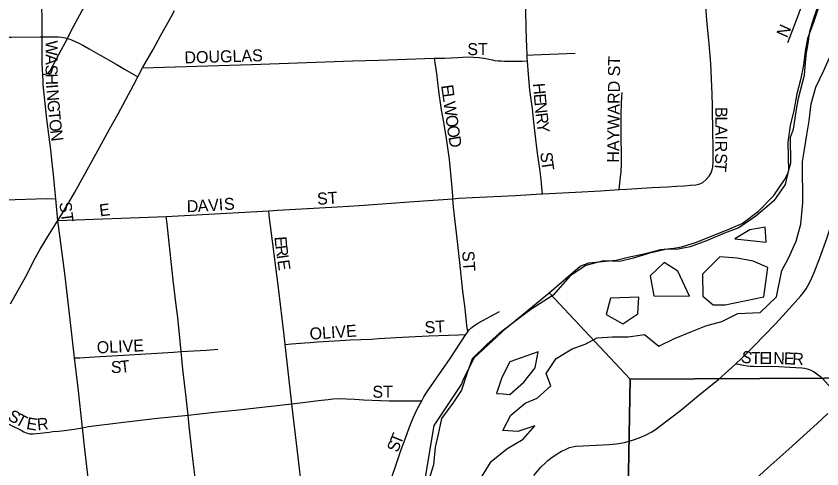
# Model space of a CAD drawing. Extents: x 0 to 34, y 0 to 22.
# Drawn here: x 5.7568 to 6.0752, y 18.8838 to 19.0628 of the extents above; entities that cross this region are included whole.
import ezdxf

# ---------------------------------------------------------------- set-up
doc = ezdxf.new("R2010")
doc.units = 0
for name, color, linetype in [('GM_X_City_Street', 7, 'Continuous'), ('GM_X_City_Street_Text', 7, 'Continuous'), ('GM_X_Major_River', 7, 'Continuous'), ('GM_X_Section', 7, 'Continuous'), ('GM_X_State_Route', 7, 'Continuous')]:
    doc.layers.add(name, color=color, linetype=linetype)

msp = doc.modelspace()

# ---------------------------------------------------------------- linework, layer by layer
at = {"layer": 'GM_X_City_Street'}
for points in [[(5.76711, 19.05456), (5.76711, 19.05656), (5.76711, 19.05942), (5.76698, 19.06897), (5.7669, 19.07523), (5.76683, 19.08435)], [(5.77708, 19.05392), (5.77875, 19.0572), (5.79185, 19.08163), (5.79313, 19.08386)], [(5.95868, 19.04734), (5.95857, 19.05106), (5.95851, 19.05324), (5.9579, 19.07557), (5.95782, 19.08191)], [(6.02935, 18.99807), (6.03057, 18.99952), (6.03139, 19.00086), (6.03185, 19.00197), (6.03209, 19.00319), (6.0322, 19.00528), (6.0322, 19.00854), (6.0322, 19.01186), (6.03208, 19.0161), (6.03191, 19.02734), (6.03185, 19.03193), (6.03128, 19.04398), (6.0306, 19.0518), (6.0303, 19.05455), (6.0302, 19.05579), (6.02994, 19.05856), (6.02972, 19.06102), (6.02913, 19.06877), (6.02892, 19.0756), (6.02877, 19.07964), (6.02867, 19.08201)], [(6.06164, 19.05235), (6.06351, 19.05704), (6.06599, 19.06372), (6.06834, 19.07008), (6.07139, 19.07917), (6.07215, 19.08178)], [(5.71316, 19.05394), (5.72122, 19.0542), (5.72943, 19.05429), (5.74165, 19.05446), (5.75484, 19.05446), (5.76633, 19.05454), (5.76711, 19.05456)], [(5.76711, 19.05456), (5.77163, 19.05463), (5.77263, 19.05461), (5.77352, 19.05456), (5.77479, 19.05442), (5.77616, 19.05417), (5.77708, 19.05392)], [(5.76731, 19.03975), (5.76723, 19.04135), (5.76712, 19.04442), (5.76711, 19.04751), (5.76711, 19.05456)], [(5.76731, 19.03975), (5.76828, 19.03983), (5.76868, 19.03993), (5.76901, 19.04005), (5.76938, 19.04028), (5.76968, 19.0405), (5.77001, 19.04085), (5.77025, 19.0412), (5.77263, 19.04567), (5.77465, 19.04928), (5.77637, 19.05253), (5.77708, 19.05392)], [(5.77708, 19.05392), (5.7772, 19.05389), (5.77799, 19.05368), (5.77874, 19.05334), (5.78154, 19.05205), (5.78321, 19.05123), (5.78566, 19.0499), (5.78942, 19.04775), (5.79635, 19.04379), (5.79969, 19.04183), (5.80311, 19.03978), (5.80488, 19.03872)], [(5.9221, 19.04609), (5.92609, 19.04619), (5.93132, 19.04643), (5.93333, 19.04656), (5.93495, 19.04664), (5.93736, 19.04655), (5.93977, 19.04635), (5.94067, 19.04625), (5.94156, 19.04612), (5.94244, 19.04597), (5.94359, 19.04575), (5.94497, 19.04544), (5.94587, 19.04525), (5.9472, 19.04512), (5.94843, 19.04507), (5.94982, 19.04497), (5.95131, 19.04502), (5.95341, 19.04497), (5.9568, 19.04502), (5.95882, 19.04505)], [(5.95868, 19.04734), (5.96105, 19.04744), (5.97765, 19.04811)], [(5.95882, 19.04505), (5.95872, 19.04615), (5.95868, 19.04734)], [(5.80678, 19.04234), (5.84987, 19.04366), (5.88987, 19.04504), (5.9001, 19.04541), (5.92193, 19.04609), (5.9221, 19.04609)], [(5.92941, 18.99058), (5.92934, 18.99156), (5.92914, 18.99497), (5.92798, 19.00608), (5.92685, 19.01438), (5.92582, 19.02082), (5.92489, 19.02569), (5.92412, 19.03121), (5.92347, 19.03643), (5.9231, 19.0392), (5.92247, 19.04349), (5.9221, 19.04609)], [(5.96476, 18.99251), (5.96453, 18.99505), (5.96426, 18.99815), (5.9637, 19.00246), (5.96295, 19.00768), (5.96257, 19.01075), (5.96217, 19.01412), (5.96139, 19.02089), (5.96076, 19.02614), (5.95979, 19.03353), (5.95919, 19.03966), (5.95882, 19.04494), (5.95882, 19.04505)], [(5.77251, 18.99059), (5.77226, 18.99324), (5.77158, 19.0002), (5.77111, 19.00481), (5.77051, 19.00993), (5.7689, 19.022), (5.76756, 19.03577), (5.76744, 19.0377), (5.76736, 19.03893), (5.76731, 19.03975)], [(5.99509, 18.99423), (5.9955, 18.99809), (5.99584, 19.0014), (5.99601, 19.00418), (5.99602, 19.00788), (5.99591, 19.01498), (5.99585, 19.02053), (5.99587, 19.02424), (5.99595, 19.02827), (5.99615, 19.03104), (5.9963, 19.03256)], [(5.99509, 18.99423), (5.99805, 18.99433), (6.00206, 18.99462), (6.00806, 18.99498), (6.01417, 18.99533), (6.01777, 18.99556), (6.02068, 18.99568), (6.0233, 18.99591), (6.0254, 18.99614), (6.02688, 18.99645), (6.02807, 18.99702), (6.02935, 18.99807)], [(6.04119, 18.92538), (6.04367, 18.92765), (6.04844, 18.93247), (6.05684, 18.94119), (6.06104, 18.94576), (6.06679, 18.95225), (6.06794, 18.95353), (6.06899, 18.95495), (6.07028, 18.95735), (6.07112, 18.95928), (6.07216, 18.96148), (6.0744, 18.96726), (6.07716, 18.97483), (6.07911, 18.98105), (6.08189, 18.99091), (6.08313, 18.99602), (6.0832, 18.99635)], [(5.92941, 18.99058), (5.93171, 18.99077), (5.93712, 18.99106), (5.95411, 18.99187), (5.96425, 18.99248), (5.96476, 18.99251)], [(5.96476, 18.99251), (5.97782, 18.99322), (5.98774, 18.99371), (5.99509, 18.99423)], [(5.74484, 18.98985), (5.75649, 18.99032), (5.76472, 18.99057), (5.76933, 18.99064), (5.77251, 18.99059)], [(5.77334, 18.98196), (5.77251, 18.99059)], [(5.85659, 18.98586), (5.8601, 18.98605), (5.88376, 18.98743), (5.89243, 18.98796), (5.91396, 18.98954), (5.92362, 18.99012), (5.92941, 18.99058)], [(5.93521, 18.93803), (5.93494, 18.94043), (5.93416, 18.94723), (5.9333, 18.954), (5.93213, 18.96541), (5.93114, 18.97368), (5.92963, 18.98724), (5.92941, 18.99058)], [(5.77334, 18.98196), (5.81611, 18.98361)], [(5.81611, 18.98361), (5.82803, 18.98428), (5.85659, 18.98586)], [(5.82203, 18.93018), (5.82065, 18.94362), (5.82009, 18.94855), (5.81891, 18.95841), (5.81723, 18.97316), (5.81643, 18.98068), (5.81611, 18.98361)], [(5.8631, 18.93303), (5.86309, 18.93314), (5.86259, 18.93777), (5.86062, 18.95437), (5.85805, 18.97379), (5.85683, 18.9839), (5.85659, 18.98586)], [(5.93521, 18.93803), (5.93523, 18.93807), (5.93595, 18.93891), (5.93644, 18.93943), (5.93696, 18.93984), (5.93761, 18.94032), (5.93829, 18.9408), (5.93943, 18.94149), (5.94777, 18.94608)], [(5.8631, 18.93303), (5.86562, 18.93323), (5.87088, 18.93365), (5.87304, 18.93381), (5.87582, 18.93402), (5.88481, 18.93459), (5.88885, 18.93476), (5.89721, 18.93515), (5.89998, 18.93532), (5.90929, 18.93584), (5.91983, 18.93643), (5.93149, 18.93684), (5.93452, 18.93695)], [(5.91704, 18.91069), (5.91793, 18.91224), (5.91939, 18.9145), (5.92171, 18.91796), (5.92826, 18.92743), (5.93452, 18.93695)], [(5.93452, 18.93695), (5.9346, 18.93709), (5.93521, 18.93803)], [(5.86578, 18.90955), (5.86564, 18.9107), (5.8631, 18.93303)], [(5.77991, 18.92766), (5.78204, 18.92777), (5.78759, 18.92807), (5.7994, 18.92877), (5.81897, 18.92992), (5.82203, 18.93018)], [(5.82203, 18.93018), (5.83201, 18.93079), (5.83647, 18.9311)], [(5.82473, 18.90511), (5.82394, 18.91211), (5.82274, 18.9232), (5.82203, 18.93018)], [(5.96138, 18.88121), (5.96413, 18.88449), (5.96592, 18.88625), (5.96687, 18.88707), (5.96812, 18.88807), (5.97063, 18.88979), (5.97229, 18.89077), (5.97355, 18.89141), (5.9755, 18.89226), (5.97778, 18.89275), (5.9808, 18.89294), (5.9911, 18.89343), (5.99406, 18.89374), (5.99715, 18.89424), (6.00034, 18.89518), (6.00295, 18.89603), (6.00544, 18.89719), (6.00793, 18.89849), (6.00936, 18.89936), (6.01065, 18.90028), (6.01935, 18.90695), (6.02647, 18.91276), (6.03264, 18.91781), (6.03432, 18.91914), (6.04119, 18.92538)], [(6.04119, 18.92538), (6.04216, 18.92519), (6.04421, 18.92477), (6.04568, 18.92451), (6.04693, 18.92439), (6.04818, 18.92437), (6.05821, 18.92425), (6.06246, 18.92403), (6.0672, 18.92371), (6.06824, 18.92357), (6.06934, 18.92334), (6.07013, 18.92308), (6.07081, 18.92281), (6.0718, 18.92232), (6.07244, 18.92195), (6.07334, 18.9213), (6.07421, 18.92062), (6.07489, 18.92002), (6.07551, 18.91937), (6.07983, 18.91459), (6.083, 18.91103)], [(5.73431, 18.9119), (5.73634, 18.91084), (5.75478, 18.90116), (5.75876, 18.89908), (5.75984, 18.8985), (5.76053, 18.89815), (5.76113, 18.89792), (5.76169, 18.89778), (5.76225, 18.89768), (5.76265, 18.8977), (5.76312, 18.89767), (5.7636, 18.8977), (5.76479, 18.89782), (5.76633, 18.89799), (5.76751, 18.8981), (5.76986, 18.89838), (5.77134, 18.89855), (5.77369, 18.89878), (5.77687, 18.89916), (5.77979, 18.8995), (5.78304, 18.9001)], [(5.86578, 18.90955), (5.87325, 18.91048), (5.87506, 18.91072), (5.87748, 18.911), (5.88014, 18.91125), (5.88195, 18.91146), (5.88441, 18.9116), (5.8872, 18.91157), (5.89062, 18.91138), (5.89401, 18.91115), (5.90423, 18.91075), (5.91415, 18.9107), (5.91704, 18.91069)], [(5.90424, 18.8775), (5.90676, 18.88476), (5.90882, 18.89109), (5.91063, 18.896), (5.91216, 18.89999), (5.91374, 18.90403), (5.91528, 18.90744), (5.91652, 18.90979), (5.91704, 18.91069)], [(5.82473, 18.90511), (5.82934, 18.90561), (5.83521, 18.90624), (5.84354, 18.90708), (5.86578, 18.90955)], [(5.86999, 18.87386), (5.86793, 18.89065), (5.8662, 18.90605), (5.86578, 18.90955)], [(5.78304, 18.9001), (5.78546, 18.90056), (5.79816, 18.90214), (5.81272, 18.90381), (5.82473, 18.90511)], [(5.82882, 18.86931), (5.82848, 18.8723), (5.82768, 18.87939), (5.82677, 18.88679), (5.82522, 18.90069), (5.82473, 18.90511)], [(6.04715, 18.87818), (6.05384, 18.88419), (6.06212, 18.89163), (6.06915, 18.89801), (6.07331, 18.90178), (6.07753, 18.90565)]]:
    msp.add_lwpolyline(points, dxfattribs=at)
at = {"layer": 'GM_X_Major_River'}
msp.add_line((6.00285, 18.95174), (5.99165, 18.95126), dxfattribs=at)
for points in [[(6.07394, 19.06656), (6.07182, 19.06031), (6.06951, 19.05387), (6.06853, 19.04894), (6.06793, 19.04343), (6.06676, 19.03756), (6.06521, 19.03206), (6.06403, 19.02542), (6.06267, 19.01955), (6.06168, 19.01291), (6.06183, 19.00702), (6.06199, 19.00189), (6.06063, 18.99621), (6.05623, 18.98978), (6.049, 18.98375), (6.04234, 18.97904), (6.03664, 18.97699), (6.02962, 18.97399), (6.02316, 18.97156), (6.01842, 18.97064), (6.01331, 18.97048), (6.00667, 18.969), (6.00079, 18.96714), (5.99529, 18.96584), (5.98885, 18.96607), (5.98183, 18.96421), (5.97574, 18.96007), (5.96895, 18.95249)], [(6.05727, 18.95181), (6.05928, 18.96223), (6.06196, 18.96715), (6.06503, 18.97378), (6.06678, 18.9806), (6.06759, 18.98895), (6.06762, 18.99389), (6.06747, 18.99977), (6.0675, 19.00528), (6.06829, 19.01002), (6.06927, 19.0159), (6.07007, 19.0214), (6.07086, 19.02804), (6.0728, 19.03467), (6.07587, 19.0413), (6.07817, 19.04622), (6.08219, 19.05284), (6.08451, 19.05947), (6.08548, 19.06421)], [(6.05298, 18.97555), (6.05276, 18.97936), (6.04669, 18.97825), (6.0408, 18.97468)], [(6.0408, 18.97468), (6.0531, 18.97347), (6.05298, 18.97555)], [(6.05223, 18.95185), (6.05379, 18.9634), (6.04794, 18.96591), (6.0417, 18.96708), (6.03488, 18.96769), (6.02805, 18.96075), (6.02813, 18.95203)], [(6.02291, 18.95207), (6.01818, 18.96191), (6.0129, 18.96536), (6.00737, 18.96007), (6.0087, 18.95218)], [(5.96895, 18.95249), (5.96013, 18.94675), (5.9544, 18.94243), (5.94772, 18.93736), (5.94276, 18.93303), (5.93703, 18.92738), (5.9349, 18.92133), (5.93276, 18.91489), (5.92931, 18.9098), (5.9249, 18.90376), (5.92353, 18.89751), (5.92235, 18.89239), (5.92173, 18.88537), (5.91979, 18.87913)], [(5.94029, 18.87992), (5.94451, 18.88672), (5.95062, 18.8918), (5.9571, 18.89554), (5.96169, 18.90082), (5.95503, 18.8986), (5.94915, 18.89902), (5.95223, 18.90507), (5.95796, 18.90977), (5.96272, 18.91182), (5.96807, 18.91671), (5.9662, 18.92147), (5.97023, 18.92751), (5.97652, 18.93126), (5.98166, 18.93312), (5.98642, 18.93555), (5.99249, 18.93607), (5.99856, 18.93603), (6.00502, 18.93693), (6.01068, 18.93233), (6.01696, 18.93532), (6.02343, 18.93793), (6.02933, 18.94035), (6.03561, 18.94201), (6.04189, 18.94519), (6.05075, 18.94569), (6.05727, 18.95181)], [(5.99165, 18.95126), (5.9899, 18.94482), (5.99651, 18.94117), (6.00242, 18.94511), (6.00285, 18.95174)], [(6.0087, 18.95218), (6.02291, 18.95207)], [(6.02813, 18.95203), (6.03224, 18.94868), (6.03698, 18.94864), (6.05223, 18.95185)], [(5.96304, 18.93003), (5.95182, 18.92613), (5.94874, 18.91989), (5.9466, 18.91365), (5.94918, 18.91345)], [(5.94918, 18.91345), (5.95191, 18.91323), (5.95745, 18.91812), (5.96186, 18.92378), (5.96304, 18.93003)]]:
    msp.add_lwpolyline(points, dxfattribs=at)
at = {"layer": 'GM_X_Section'}
for points in [[(6.51159, 18.92185), (5.99942, 18.91928), (5.96741, 18.95343), (5.97962, 18.96399), (5.98304, 18.96529), (5.99385, 18.96634), (5.99859, 18.96744), (6.00543, 18.9689), (6.0115, 18.97056), (6.01662, 18.97109), (6.01966, 18.97164), (6.02517, 18.9733), (6.03752, 18.97813), (6.0436, 18.98074), (6.05008, 18.98562), (6.05619, 18.99182), (6.06041, 18.99804), (6.06175, 19.0005), (6.06292, 19.00484), (6.06281, 19.01489), (6.06397, 19.0181), (6.06497, 19.0251), (6.06596, 19.0304), (6.0683, 19.03948), (6.06893, 19.04743), (6.06972, 19.05197), (6.07033, 19.0567), (6.07188, 19.06162), (6.07944, 19.08354)], [(5.751, 18.66593), (5.77962, 18.69224), (5.79353, 18.70237), (5.81311, 18.71094), (5.83598, 18.72819), (5.85394, 18.74739), (5.86623, 18.76965), (5.88363, 18.79055), (5.90361, 18.82773), (5.91254, 18.85494), (5.91525, 18.86288), (5.91821, 18.87821), (5.92198, 18.90091), (5.93271, 18.91713), (5.93348, 18.91883), (5.93772, 18.9277), (5.9505, 18.93954), (5.96741, 18.95343), (5.99942, 18.91928), (5.99052, 18.41894), (5.46396, 18.4161)]]:
    msp.add_lwpolyline(points, dxfattribs=at)
msp.add_lwpolyline([(6.51159, 18.92185), (6.50305, 18.41943), (5.99052, 18.41894), (5.99942, 18.91928)], close=True, dxfattribs=at)
at = {"layer": 'GM_X_State_Route'}
for points in [[(5.75459, 18.94902), (5.76059, 18.95988), (5.76437, 18.96716), (5.76634, 18.97069), (5.76811, 18.97374), (5.76934, 18.97567), (5.77334, 18.98196), (5.7751, 18.98494), (5.77852, 18.99075), (5.77995, 18.99318), (5.789, 19.00937), (5.79376, 19.0181), (5.79709, 19.0242), (5.80319, 19.0355), (5.80488, 19.03872), (5.80678, 19.04234), (5.81091, 19.04963), (5.81382, 19.05492), (5.81802, 19.06252), (5.81944, 19.06505)], [(5.79616, 18.7827), (5.79563, 18.78766), (5.79514, 18.7922), (5.79507, 18.79286), (5.79209, 18.8194), (5.79098, 18.82901), (5.78924, 18.84409), (5.78704, 18.86451), (5.78647, 18.86989), (5.78386, 18.89283), (5.78304, 18.9001), (5.78127, 18.91585), (5.77991, 18.92766), (5.77817, 18.94285), (5.77605, 18.96105), (5.77334, 18.98196)]]:
    msp.add_lwpolyline(points, dxfattribs=at)

# ---------------------------------------------------------------- texts
at = {"layer": 'GM_X_City_Street_Text'}
for s, height, rotation, p in [('N', 0.00473, 66.0262, (6.06135, 19.05391)), ('W', 0.00473, 270.0336, (5.76847, 19.05313)), ('DOUGLAS', 0.004735, 1.7348, (5.82338, 19.04402)), ('ST', 0.004735, 0, (5.93508, 19.04735)), ('A', 0.00473, 270.0379, (5.76847, 19.04771)), ('HAYWARD ST', 0.004735, 89.3903, (5.99502, 19.00482)), ('S', 0.00473, 270.0455, (5.76847, 19.04354)), ('H', 0.00473, 272.0108, (5.76848, 19.04003)), ('I', 0.00473, 274.3992, (5.76864, 19.03566)), ('E', 0.00473, 277.9756, (5.92471, 19.03533)), ('H', 0.00473, 274.7709, (5.96096, 19.03612)), ('N', 0.00473, 274.5306, (5.7688, 19.03357)), ('L', 0.00473, 278.0001, (5.92517, 19.03203)), ('E', 0.00473, 274.7903, (5.96131, 19.03197)), ('G', 0.00473, 274.553, (5.76913, 19.02941)), ('W', 0.00473, 277.9779, (5.92563, 19.02873)), ('N', 0.00473, 275.7737, (5.9616, 19.02856)), ('T', 0.00473, 275.0945, (5.76946, 19.02521)), ('R', 0.00473, 277.0689, (5.96203, 19.0243)), ('B', 0.00473, 269.7814, (6.03305, 19.02688)), ('O', 0.00473, 276.9381, (5.76978, 19.02172)), ('O', 0.00473, 277.9986, (5.92639, 19.02336)), ('Y', 0.00473, 277.1445, (5.96249, 19.02057)), ('L', 0.00473, 269.769, (6.03304, 19.02314)), ('O', 0.00473, 278.193, (5.92697, 19.01922)), ('A', 0.00473, 269.7595, (6.03302, 19.0198)), ('N', 0.00473, 277.3361, (5.77028, 19.01755)), ('D', 0.00473, 279.7518, (5.92759, 19.01496)), ('I', 0.00473, 269.7919, (6.03301, 19.01564)), ('R', 0.00473, 269.7814, (6.033, 19.01355)), ('S', 0.00473, 275.7188, (5.96389, 19.00884)), ('S', 0.00473, 269.7814, (6.03298, 19.00855)), ('T', 0.00473, 277.9251, (5.96425, 19.00532)), ('T', 0.00473, 264.3084, (6.03297, 19.00534)), ('ST', 0.004735, 3.5746, (5.87585, 18.98818)), ('D', 0.00473, 0.9399, (5.82426, 18.98527)), ('A', 0.00473, 3.6255, (5.82867, 18.98535)), ('V', 0.00473, 3.9761, (5.83286, 18.98561)), ('I', 0.00473, 3.9838, (5.83702, 18.9859)), ('S', 0.00473, 3.9922, (5.8391, 18.98605)), ('ST', 0.004735, 277.1217, (5.77388, 18.98907)), ('E', 0.00473, 7.1217, (5.78997, 18.98359)), ('E', 0.00473, 274.8408, (5.85889, 18.97552)), ('R', 0.00473, 277.8913, (5.8592, 18.97193)), ('I', 0.00473, 278.1402, (5.85971, 18.9682)), ('ST', 0.004735, 273.5746, (5.93305, 18.96985)), ('E', 0.00473, 278.1537, (5.86001, 18.96613)), ('ST', 0.004735, 3.5738, (5.91835, 18.93735)), ('OLIVE', 0.004735, 3.9917, (5.87293, 18.93485)), ('OLIVE', 0.004735, 2.7248, (5.78878, 18.92944)), ('S', 0.00473, 348.9741, (6.04292, 18.92604)), ('T', 0.00473, 359.3044, (6.04712, 18.92531)), ('E', 0.00473, 359.9322, (6.05051, 18.92527)), ('I', 0.00473, 359.9563, (6.05384, 18.92527)), ('N', 0.00473, 359.0164, (6.05591, 18.92526)), ('E', 0.00473, 357.5947, (6.06004, 18.92519)), ('R', 0.00473, 357.5221, (6.06337, 18.92505)), ('S', 0.00473, 0.3005, (5.79425, 18.92171)), ('T', 0.00473, 6.4593, (5.79814, 18.92176)), ('ST', 0.004735, 0, (5.89758, 18.91194)), ('S', 0.00473, 331.516, (5.75317, 18.90336)), ('T', 0.00473, 331.5468, (5.75611, 18.90177)), ('E', 0.00473, 350.2003, (5.76062, 18.89963)), ('R', 0.00473, 5.8635, (5.76531, 18.89901)), ('T', 0.00473, 67.5441, (5.90873, 18.8931)), ('S', 0.00473, 68.9546, (5.90754, 18.89002))]:
    msp.add_text(s, height=height, rotation=rotation, dxfattribs=at).set_placement(p)

doc.saveas('drawing.dxf')
